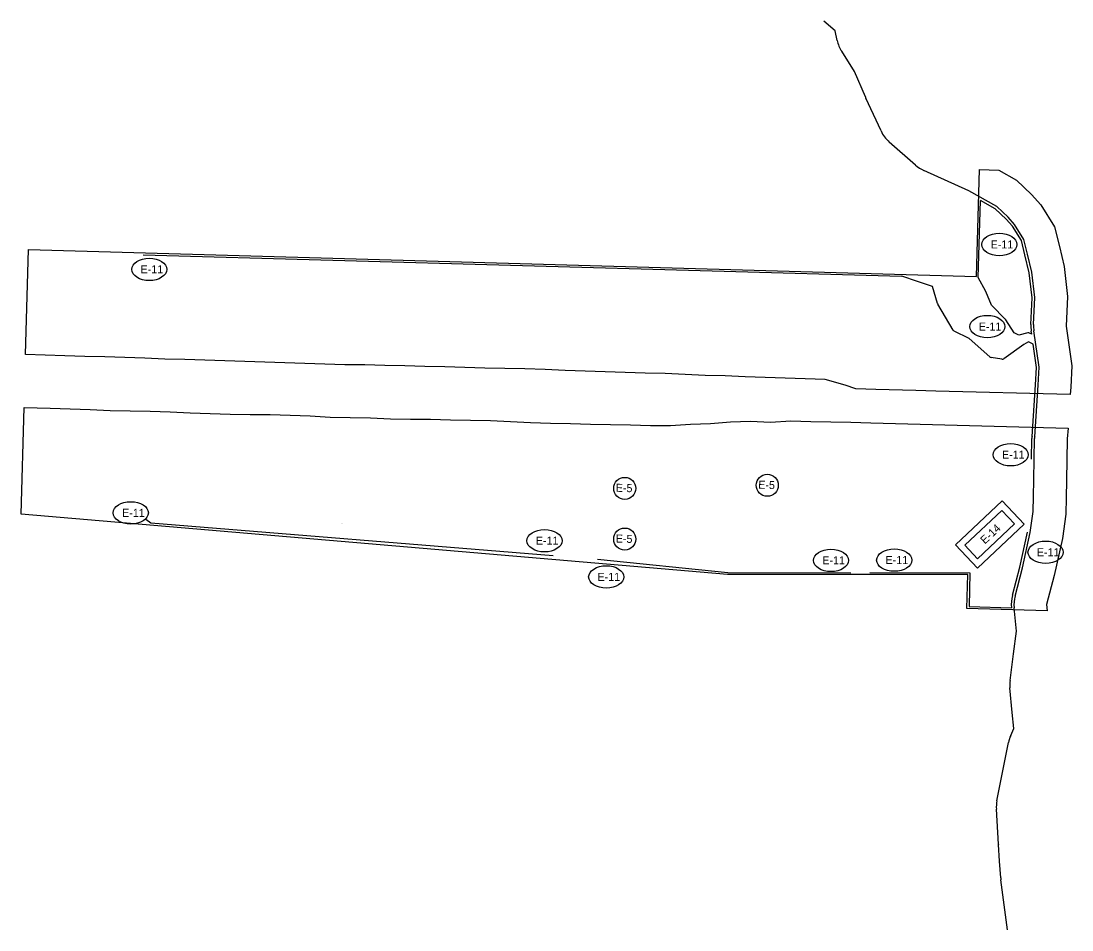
# Model space of a CAD drawing. Extents: x 977239 to 983725, y 1525948 to 1526901.
# Drawn here: x 982116 to 982904, y 1525948 to 1526629 of the extents above; entities that cross this region are included whole.
import ezdxf

# ---------------------------------------------------------------- set-up
doc = ezdxf.new("R2010")
doc.units = 0
for name, color, linetype in [('R_Erosion', 7, 'Continuous'), ('R_No Plot', 7, 'Continuous'), ('R_Water', 7, 'Continuous')]:
    doc.layers.add(name, color=color, linetype=linetype)

msp = doc.modelspace()

# ---------------------------------------------------------------- linework, layer by layer
at = {"layer": 'R_Erosion'}
for p, q in [((982833.79, 1526436.84), (982835.43, 1526494.67)), ((982207.86, 1526453.97), (982776.45, 1526437.86)), ((982839.42, 1526426.51), (982833.79, 1526436.84)), ((982814.94, 1526397.41), (982803.49, 1526416.92)), ((982873.78, 1526394.55), (982872.23, 1526395.31)), ((982851.45, 1526375.71), (982843.3, 1526377.01)), ((982209.98, 1526255.83), (982213.7, 1526253.2)), ((982213.7, 1526253.2), (982515.22, 1526228.62)), ((982548.38, 1526225.92), (982646.01, 1526215.95)), ((982646.01, 1526215.95), (982738.21, 1526215.59)), ((982752.59, 1526215.86), (982827.53, 1526215.74)), ((982827.53, 1526215.74), (982826.81, 1526190.33)), ((982826.81, 1526190.33), (982858.61, 1526189.43))]:
    msp.add_line(p, q, dxfattribs=at)
for points in [[(982873.23, 1526401.69), (982874.1, 1526421.77), (982871.99, 1526440.45), (982868.75, 1526453.79), (982866.14, 1526464.52), (982859.3, 1526475.42), (982854.62, 1526480.63), (982846.48, 1526488.42), (982835.43, 1526494.67)], [(982803.3, 1526417.34), (982799.35, 1526430.15), (982788.1, 1526433.94), (982776.45, 1526437.86)], [(982854.21, 1526405.55), (982843.76, 1526416.06), (982839.51, 1526426.32)], [(982870.84, 1526395.44), (982864.19, 1526393.69), (982860.54, 1526395.43), (982854.49, 1526405.19)], [(982842.29, 1526377.5), (982827, 1526391.2), (982815.79, 1526396.63)], [(982873.78, 1526394.55), (982873.47, 1526396.71)], [(982874.87, 1526386.91), (982871.36, 1526388.73), (982867.97, 1526386.58), (982852.92, 1526376.05)], [(982874.03, 1526317.73), (982876.62, 1526356.46), (982877.36, 1526369.5), (982874.87, 1526386.91)], [(982873.72, 1526300.87), (982873.98, 1526316.38)], [(982859.37, 1526198.76), (982864.85, 1526219.8), (982870.68, 1526246.21)]]:
    msp.add_lwpolyline(points, dxfattribs=at)
for points in [[(982816.65, 1526236.68), (982851.68, 1526269.5), (982868.09, 1526251.98), (982833.05, 1526219.17)], [(982823.71, 1526236.45), (982851.45, 1526262.43), (982861.02, 1526252.21), (982833.28, 1526226.23)]]:
    msp.add_lwpolyline(points, close=True, dxfattribs=at)
for centre in [(982568.87, 1526278.9), (982675.64, 1526281.22), (982568.87, 1526240.88)]:
    msp.add_circle(centre, 8.26, dxfattribs=at)
for centre, radius, start, end in [((982837.67, 1526425.55), 2, 22.4761, 28.60038), ((982805.21, 1526417.93), 2, 197.1439, 210.42381), ((982852.79, 1526404.14), 2, 31.80254, 44.82964), ((982816.67, 1526398.43), 2, 210.42381, 244.15156), ((982900.2, 1526400.53), 27, 177.52615, 188.13145), ((982871.35, 1526393.51), 2, 63.96612, 104.73743), ((982843.62, 1526378.99), 2, 228.14009, 260.91658), ((982851.77, 1526377.69), 2, 260.91658, 304.97622), ((982900.97, 1526315.94), 27, 176.18338, 179.06048), ((982885.5, 1526191.95), 27, 165.39722, 185.35936)]:
    msp.add_arc(centre, radius, start, end, dxfattribs=at)
for centre in [(982849.51, 1526461.61), (982212.5, 1526442.97), (982840.59, 1526400.1), (982858.03, 1526304.13), (982198.7, 1526260.52), (982508.7, 1526239.68), (982884.16, 1526231), (982723.39, 1526224.94), (982770.76, 1526225.15), (982554.94, 1526212.54)]:
    msp.add_ellipse(centre, major_axis=(13.15, 0), ratio=0.638788, dxfattribs=at)
at = {"layer": 'R_No Plot'}
for p, q in [((982832.32, 1526437.77), (982834.58, 1526517.74)), ((982834.58, 1526517.74), (982849.19, 1526517.33)), ((982119.86, 1526379.11), (982122.12, 1526457.9)), ((982122.12, 1526457.9), (982832.32, 1526437.77)), ((982116.43, 1526259.45), (982118.73, 1526339.57)), ((982645.87, 1526214.45), (982116.43, 1526259.45)), ((982825.98, 1526214.3), (982645.87, 1526214.45)), ((982825.26, 1526188.87), (982825.98, 1526214.3)), ((982885.47, 1526187.17), (982825.26, 1526188.87))]:
    msp.add_line(p, q, dxfattribs=at)
for points in [[(982849.19, 1526517.33), (982862.41, 1526509.85), (982873.67, 1526499.09), (982880.54, 1526491.43), (982890.88, 1526474.96), (982894.5, 1526460.04), (982898.13, 1526445.08), (982900.66, 1526422.69), (982899.7, 1526400.5), (982903.97, 1526370.64), (982903.07, 1526354.82), (982902.69, 1526349.18)], [(982902.69, 1526349.18), (982802.02, 1526351.67), (982787.03, 1526352.13), (982757.04, 1526352.97), (982742.12, 1526353.58), (982733.97, 1526356.14), (982719.01, 1526360.56), (982704.08, 1526361.03), (982689.08, 1526361.41), (982674.1, 1526361.97), (982659.11, 1526362.57), (982644.12, 1526363.17), (982629.12, 1526363.58), (982614.03, 1526364.17), (982599.05, 1526364.93), (982584.05, 1526365.34), (982569.05, 1526365.76), (982554.06, 1526366.27), (982539.07, 1526366.71), (982524.08, 1526367.25), (982509.08, 1526367.84), (982494.08, 1526368.37), (982479.08, 1526368.72), (982464.09, 1526369.07), (982449.09, 1526369.46), (982434.1, 1526369.84), (982419.1, 1526370.16), (982404.11, 1526370.59), (982389.11, 1526370.94), (982374.12, 1526371.41), (982359.15, 1526371.58), (982344.17, 1526372.05), (982329.18, 1526372.55), (982314.18, 1526373.04), (982299.19, 1526373.45), (982284.2, 1526374), (982269.2, 1526374.46), (982254.21, 1526374.94), (982239.22, 1526375.36), (982224.28, 1526375.83), (982209.29, 1526376.48), (982194.29, 1526376.94), (982179.3, 1526377.36), (982164.31, 1526377.81), (982149.31, 1526378.22), (982119.86, 1526379.11)], [(982118.73, 1526339.57), (982138.25, 1526338.99), (982153.24, 1526338.5), (982168.23, 1526338.03), (982183.22, 1526337.32), (982198.22, 1526337.06), (982213.21, 1526336.7), (982228.2, 1526336.14), (982243.23, 1526335.5), (982258.22, 1526334.91), (982273.22, 1526334.54), (982288.22, 1526334.19), (982303.23, 1526334.13), (982318.21, 1526333.79), (982333.2, 1526333.19), (982348.18, 1526332.36), (982363.19, 1526331.95), (982378.21, 1526331.73), (982393.2, 1526331.08), (982408.21, 1526330.74), (982423.21, 1526330.71), (982438.19, 1526330.14), (982453.2, 1526329.89), (982468.19, 1526329.65), (982483.17, 1526328.99), (982498.16, 1526328.33), (982513.14, 1526327.76), (982528.14, 1526327.39), (982543.14, 1526327.07), (982558.14, 1526326.83), (982573.13, 1526326.48), (982588.13, 1526326.03), (982603.16, 1526325.96), (982618.11, 1526326.99), (982633.15, 1526327.62), (982648.19, 1526328.81), (982663.18, 1526329.14), (982678.17, 1526328.58), (982693.21, 1526329.44), (982708.19, 1526328.98), (982723.26, 1526328.74), (982738.25, 1526328.44), (982753.25, 1526328.08), (982901.02, 1526324.05)], [(982901.02, 1526324.05), (982900.48, 1526315.96), (982899.97, 1526284.85), (982899.68, 1526272.18), (982899.39, 1526259.54), (982896.77, 1526241.45), (982890.62, 1526213.6), (982884.99, 1526191.99), (982885.47, 1526187.17)]]:
    msp.add_lwpolyline(points, dxfattribs=at)
for centre in [(982568.87, 1526278.9), (982568.87, 1526240.88)]:
    msp.add_circle(centre, 8.26, dxfattribs=at)
for centre in [(982198.7, 1526260.52), (982508.7, 1526239.68), (982884.16, 1526231), (982723.39, 1526224.94), (982770.76, 1526225.15)]:
    msp.add_ellipse(centre, major_axis=(13.15, 0), ratio=0.638788, dxfattribs=at)
at = {"layer": 'R_Water'}
for p, q in [((982760.88, 1526546.67), (982749.49, 1526571.33)), ((982786.61, 1526521.17), (982767.06, 1526538.37)), ((982847.73, 1526044.83), (982856.35, 1526088.41)), ((982848.83, 1526012.29), (982847.3, 1526038.52))]:
    msp.add_line(p, q, dxfattribs=at)
for points in [[(982727.99, 1526614.55), (982726.41, 1526621.75), (982717.99, 1526629.07)], [(982749.13, 1526572.16), (982741.1, 1526591.34), (982731.4, 1526606.36)], [(982875.23, 1526401.61), (982876.1, 1526421.84), (982873.96, 1526440.8), (982870.69, 1526454.26), (982868.01, 1526465.3), (982860.9, 1526476.63), (982856.06, 1526482.03), (982847.68, 1526490.03), (982826.68, 1526501.92), (982792.86, 1526517.15)], [(982876.03, 1526317.6), (982878.61, 1526356.33), (982879.37, 1526369.59), (982875.45, 1526396.99)], [(982861.3, 1526198.25), (982866.79, 1526219.33), (982872.65, 1526245.85), (982874.93, 1526261.59), (982875.18, 1526272.74), (982875.47, 1526285.33), (982875.98, 1526316.34)], [(982857.55, 1526135.07), (982860.15, 1526154.95), (982862.37, 1526171.97), (982860.62, 1526189.47)], [(982858.05, 1526093.77), (982860.33, 1526098.87), (982859.2, 1526110.9), (982857.45, 1526129.49)], [(982850.61, 1525987.02), (982849.73, 1525999.51), (982848.85, 1526012)], [(982855.66, 1525948.02), (982853.21, 1525966.77), (982850.76, 1525985.52)]]:
    msp.add_lwpolyline(points, dxfattribs=at)
for centre, start, end in [((982752.41, 1526619.92), 192.39926, 212.84175), ((982772.19, 1526581.81), 202.71046, 204.77072), ((982783.58, 1526557.14), 204.77072, 228.66213), ((982803.13, 1526539.94), 228.66213, 245.75073), ((982900.2, 1526400.53), 177.52615, 188.13145), ((982900.97, 1526315.94), 176.18338, 179.06048), ((982885.5, 1526191.95), 165.39722, 185.70892), ((982882.34, 1526131.83), 172.56379, 185.37559), ((982880.87, 1526083.56), 155.89018, 168.81529), ((982872.26, 1526039.98), 168.81529, 183.347), ((982873.79, 1526013.75), 183.347, 184.02042), ((982875.54, 1525988.77), 184.01554, 187.4527)]:
    msp.add_arc(centre, 25, start, end, dxfattribs=at)

# ---------------------------------------------------------------- texts
at = {"layer": 'R_Erosion'}
for p in [(982843.01, 1526458.66), (982206.01, 1526440.02), (982834.09, 1526397.15), (982851.53, 1526301.18), (982192.2, 1526257.57), (982502.2, 1526236.73), (982877.66, 1526228.05), (982716.89, 1526221.99), (982764.26, 1526222.2), (982548.44, 1526209.59)]:
    msp.add_text('E-11', height=5.999, dxfattribs=at).set_placement(p)
for s, height, rotation, p in [('E-5 ', 5.999, 358.09005, (982562.02, 1526276.4)), ('E-5 ', 5.999, 358.09005, (982668.79, 1526278.72)), ('E-14', 6, 43.12573, (982838.69, 1526236.78)), ('E-5 ', 5.999, 358.09005, (982562.02, 1526238.38))]:
    msp.add_text(s, height=height, rotation=rotation, dxfattribs=at).set_placement(p)
at = {"layer": 'R_Water'}
for rotation, p in [(0.22334, (982465.36, 1526395.01)), (356.69945, (982356.23, 1526252.28))]:
    msp.add_text('CONST. LIMITS', height=0.12, rotation=rotation, dxfattribs=at).set_placement(p)

doc.saveas('drawing.dxf')
